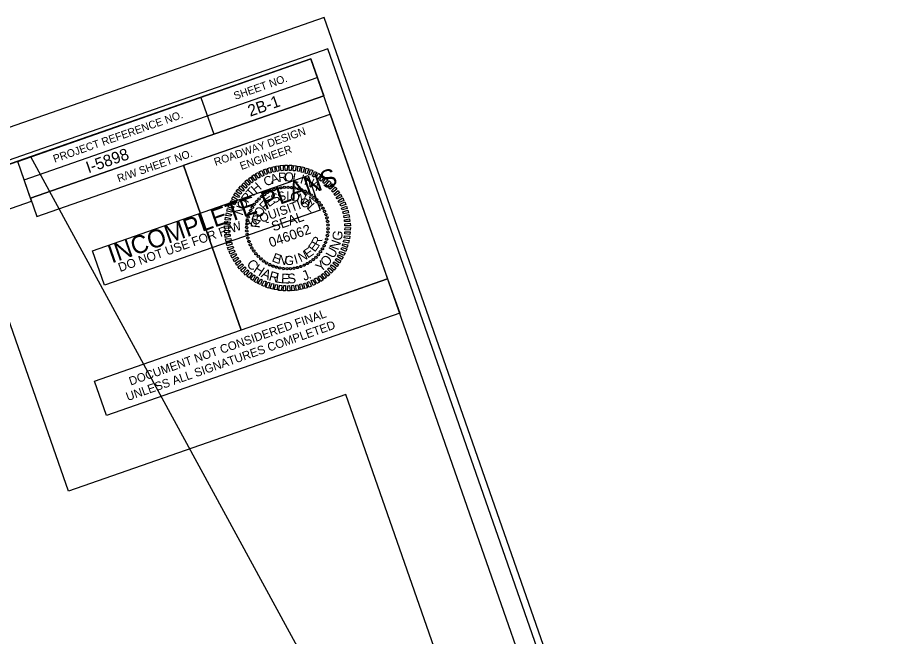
# Model space of a CAD drawing. Extents: x 1721700 to 1723652, y 970581 to 972169.
# Drawn here: x 1723091 to 1723650, y 971770 to 972169 of the extents above; entities that cross this region are included whole.
import ezdxf

# ---------------------------------------------------------------- set-up
doc = ezdxf.new("R2010")
doc.units = 0
for name, color, linetype in [('Default', 7, 'Continuous'), ('Old_Level_2', 7, 'Continuous'), ('Prop Dimension Text', 7, 'Continuous'), ('Sheet Clip Boundary CELL', 7, 'Continuous'), ('Sheet Data Field CELL', 7, 'Continuous'), ('Sheet Plan CELL', 7, 'Continuous'), ('Sheet Plot Border Inside CELL', 7, 'Continuous'), ('Sheet Plot Border Outside CELL', 7, 'Continuous'), ('Sheet Sticker Exception Certification CELL', 7, 'Continuous'), ('Sheet Sticker Incomplete CELL', 7, 'Continuous')]:
    doc.layers.add(name, color=color, linetype=linetype)

msp = doc.modelspace()

# ---------------------------------------------------------------- linework, layer by layer
at = {"layer": 'Old_Level_2'}
for p, q in [((1723261, 972059.49), (1723261, 972059.49)), ((1723263.22, 972059.81), (1723263.22, 972059.81)), ((1723265.54, 972059.89), (1723265.54, 972059.89)), ((1723267.83, 972059.73), (1723267.83, 972059.73)), ((1723270.1, 972059.45), (1723270.1, 972059.45)), ((1723248.55, 972053.95), (1723248.55, 972053.95)), ((1723250.4, 972055.3), (1723250.4, 972055.3)), ((1723252.41, 972056.49), (1723252.41, 972056.49)), ((1723254.41, 972057.56), (1723254.41, 972057.56)), ((1723256.55, 972058.41), (1723256.55, 972058.41)), ((1723258.77, 972059.06), (1723258.77, 972059.06)), ((1723272.32, 972058.88), (1723272.32, 972058.88)), ((1723274.53, 972058.18), (1723274.53, 972058.18)), ((1723276.59, 972057.27), (1723276.59, 972057.27)), ((1723278.66, 972056.2), (1723278.66, 972056.2)), ((1723280.52, 972054.93), (1723280.52, 972054.93)), ((1723243.88, 972048.94), (1723243.88, 972048.94)), ((1723245.33, 972050.76), (1723245.33, 972050.76)), ((1723246.88, 972052.44), (1723246.88, 972052.44)), ((1723282.33, 972053.49), (1723282.33, 972053.49)), ((1723284.02, 972051.93), (1723284.02, 972051.93)), ((1723285.53, 972050.26), (1723285.53, 972050.26)), ((1723286.88, 972048.42), (1723286.88, 972048.42)), ((1723240.63, 972042.95), (1723240.63, 972042.95)), ((1723241.54, 972045.01), (1723241.54, 972045.01)), ((1723242.62, 972047.08), (1723242.62, 972047.08)), ((1723288.07, 972046.4), (1723288.07, 972046.4)), ((1723289.14, 972044.4), (1723289.14, 972044.4)), ((1723239.37, 972038.53), (1723239.37, 972038.53)), ((1723239.94, 972040.74), (1723239.94, 972040.74)), ((1723289.99, 972042.26), (1723289.99, 972042.26)), ((1723290.63, 972040.05), (1723290.63, 972040.05)), ((1723291.07, 972037.81), (1723291.07, 972037.81)), ((1723238.93, 972033.96), (1723238.93, 972033.96)), ((1723239, 972031.65), (1723239, 972031.65)), ((1723239.09, 972036.25), (1723239.09, 972036.25)), ((1723265.2, 972033.62), (1723265.2, 972033.62)), ((1723291.39, 972035.59), (1723291.39, 972035.59)), ((1723291.46, 972033.28), (1723291.46, 972033.28)), ((1723239.32, 972029.43), (1723239.32, 972029.43)), ((1723239.76, 972027.19), (1723239.76, 972027.19)), ((1723290.45, 972026.5), (1723290.45, 972026.5)), ((1723291.03, 972028.71), (1723291.03, 972028.71)), ((1723291.3, 972030.99), (1723291.3, 972030.99)), ((1723240.41, 972024.98), (1723240.41, 972024.98)), ((1723241.25, 972022.84), (1723241.25, 972022.84)), ((1723242.32, 972020.84), (1723242.32, 972020.84)), ((1723287.77, 972020.16), (1723287.77, 972020.16)), ((1723288.85, 972022.23), (1723288.85, 972022.23)), ((1723289.76, 972024.29), (1723289.76, 972024.29)), ((1723243.51, 972018.82), (1723243.51, 972018.82)), ((1723244.86, 972016.98), (1723244.86, 972016.98)), ((1723246.37, 972015.31), (1723246.37, 972015.31)), ((1723283.51, 972014.79), (1723283.51, 972014.79)), ((1723285.06, 972016.48), (1723285.06, 972016.48)), ((1723286.51, 972018.3), (1723286.51, 972018.3)), ((1723248.06, 972013.75), (1723248.06, 972013.75)), ((1723249.87, 972012.31), (1723249.87, 972012.31)), ((1723251.73, 972011.04), (1723251.73, 972011.04)), ((1723253.8, 972009.97), (1723253.8, 972009.97)), ((1723255.87, 972009.06), (1723255.87, 972009.06)), ((1723275.98, 972009.68), (1723275.98, 972009.68)), ((1723277.98, 972010.75), (1723277.98, 972010.75)), ((1723279.99, 972011.94), (1723279.99, 972011.94)), ((1723281.84, 972013.29), (1723281.84, 972013.29)), ((1723258.07, 972008.36), (1723258.07, 972008.36)), ((1723260.29, 972007.79), (1723260.29, 972007.79)), ((1723262.57, 972007.51), (1723262.57, 972007.51)), ((1723264.85, 972007.35), (1723264.85, 972007.35)), ((1723267.17, 972007.43), (1723267.17, 972007.43)), ((1723269.39, 972007.75), (1723269.39, 972007.75)), ((1723271.63, 972008.18), (1723271.63, 972008.18)), ((1723273.84, 972008.83), (1723273.84, 972008.83))]:
    msp.add_line(p, q, dxfattribs=at)
for points in [[(1723248.79, 972066.91), (1723247.09, 972069.86), (1723248.69, 972070.67), (1723249.91, 972067.5)], [(1723251.15, 972068.06), (1723249.73, 972071.16), (1723251.37, 972071.71), (1723252.35, 972068.45)], [(1723253.52, 972068.88), (1723252.35, 972072.07), (1723253.98, 972072.62), (1723254.72, 972069.27)], [(1723256.03, 972069.64), (1723255.05, 972072.9), (1723256.78, 972073.21), (1723257.28, 972069.88)], [(1723258.53, 972070.12), (1723257.81, 972073.42), (1723259.52, 972073.77), (1723259.76, 972070.41)], [(1723261.23, 972070.5), (1723260.55, 972073.87), (1723262.36, 972074.09), (1723262.35, 972070.64)], [(1723263.82, 972070.73), (1723263.44, 972074.05), (1723265.14, 972074.12), (1723264.98, 972070.77)], [(1723266.36, 972070.66), (1723266.34, 972074.17), (1723267.93, 972074.09), (1723267.61, 972070.74)], [(1723268.91, 972070.55), (1723269.07, 972073.89), (1723270.84, 972073.77), (1723270.18, 972070.4)], [(1723271.58, 972070.25), (1723271.87, 972073.54), (1723273.65, 972073.24), (1723272.73, 972070.01)], [(1723273.98, 972069.63), (1723274.65, 972073.11), (1723276.3, 972072.55), (1723275.28, 972069.44)], [(1723276.54, 972068.9), (1723277.36, 972072.27), (1723279.03, 972071.66), (1723277.72, 972068.56)], [(1723278.96, 972068.07), (1723280.03, 972071.36), (1723281.64, 972070.62), (1723280.16, 972067.68)], [(1723242.27, 972062.84), (1723240.05, 972065.36), (1723241.41, 972066.37), (1723243.17, 972063.56)], [(1723244.39, 972064.34), (1723242.22, 972067.05), (1723243.76, 972068.01), (1723245.33, 972064.97)], [(1723246.54, 972065.75), (1723244.6, 972068.6), (1723246.16, 972069.35), (1723247.67, 972066.33)], [(1723281.36, 972067), (1723282.62, 972070.09), (1723284.23, 972069.34), (1723282.39, 972066.49)], [(1723283.73, 972065.87), (1723285.17, 972068.91), (1723286.69, 972067.97), (1723284.78, 972065.14)], [(1723285.91, 972064.5), (1723287.55, 972067.45), (1723289.01, 972066.37), (1723286.84, 972063.79)], [(1723287.92, 972062.96), (1723289.84, 972065.78), (1723291.31, 972064.66), (1723288.97, 972062.23)], [(1723236.7, 972057.38), (1723233.91, 972059.36), (1723235.14, 972060.71), (1723237.42, 972058.32)], [(1723238.38, 972059.34), (1723235.79, 972061.51), (1723237.06, 972062.75), (1723239.29, 972060.18)], [(1723240.15, 972061.17), (1723237.83, 972063.54), (1723239.08, 972064.67), (1723241.27, 972061.91)], [(1723290, 972061.27), (1723292.11, 972064), (1723293.31, 972062.72), (1723290.93, 972060.56)], [(1723291.75, 972059.52), (1723294.11, 972062.06), (1723295.32, 972060.73), (1723292.64, 972058.63)], [(1723293.49, 972057.54), (1723296.01, 972059.92), (1723297.11, 972058.6), (1723294.36, 972056.7)], [(1723232.27, 972050.96), (1723229.32, 972052.32), (1723230.06, 972053.93), (1723232.95, 972051.99)], [(1723233.67, 972053.2), (1723230.69, 972054.78), (1723231.64, 972056.3), (1723234.37, 972054.18)], [(1723234.99, 972055.36), (1723232.26, 972057.19), (1723233.19, 972058.6), (1723235.86, 972056.35)], [(1723295.14, 972055.48), (1723297.87, 972057.77), (1723298.76, 972056.26), (1723295.87, 972054.58)], [(1723296.6, 972053.34), (1723299.35, 972055.41), (1723300.26, 972053.85), (1723297.27, 972052.42)], [(1723230.26, 972046.14), (1723227, 972047.12), (1723227.61, 972048.79), (1723230.62, 972047.28)], [(1723231.29, 972048.64), (1723228.04, 972049.73), (1723228.85, 972051.31), (1723231.78, 972049.72)], [(1723297.91, 972051.15), (1723300.84, 972053.01), (1723301.61, 972051.4), (1723298.54, 972050.05)], [(1723299.07, 972048.9), (1723302.12, 972050.47), (1723302.83, 972048.84), (1723299.6, 972047.76)], [(1723228.73, 972041.23), (1723225.44, 972041.69), (1723225.91, 972043.43), (1723229.18, 972042.4)], [(1723229.47, 972043.74), (1723226.21, 972044.43), (1723226.62, 972046.19), (1723229.77, 972044.9)], [(1723300.03, 972046.47), (1723303.16, 972047.79), (1723303.78, 972046.12), (1723300.46, 972045.29)], [(1723300.88, 972044), (1723304.11, 972045.08), (1723304.61, 972043.42), (1723301.22, 972042.78)], [(1723301.51, 972041.55), (1723304.75, 972042.42), (1723305.17, 972040.68), (1723301.69, 972040.29)], [(1723228.18, 972036.07), (1723224.72, 972036.08), (1723224.89, 972037.87), (1723228.27, 972037.33)], [(1723228.33, 972038.69), (1723225.08, 972038.88), (1723225.25, 972040.68), (1723228.57, 972039.84)], [(1723302.04, 972038.91), (1723305.22, 972039.64), (1723305.49, 972037.84), (1723302.02, 972037.73)], [(1723228.13, 972030.92), (1723224.85, 972030.44), (1723224.59, 972032.18), (1723228.14, 972032.1)], [(1723227.99, 972033.55), (1723224.63, 972033.31), (1723224.7, 972035.07), (1723228.15, 972034.78)], [(1723302.4, 972033.69), (1723305.77, 972033.93), (1723305.69, 972032.17), (1723302.24, 972032.46)], [(1723302.27, 972036.32), (1723305.54, 972036.8), (1723305.8, 972035.06), (1723302.25, 972035.14)], [(1723228.36, 972028.33), (1723225.17, 972027.6), (1723224.9, 972029.4), (1723228.37, 972029.51)], [(1723228.89, 972025.69), (1723225.64, 972024.82), (1723225.22, 972026.56), (1723228.7, 972026.95)], [(1723301.67, 972026.01), (1723304.96, 972025.55), (1723304.48, 972023.81), (1723301.21, 972024.83)], [(1723302.07, 972028.55), (1723305.32, 972028.36), (1723305.14, 972026.56), (1723301.82, 972027.4)], [(1723302.22, 972031.17), (1723305.67, 972031.16), (1723305.5, 972029.37), (1723302.12, 972029.91)], [(1723229.51, 972023.24), (1723226.29, 972022.16), (1723225.79, 972023.82), (1723229.17, 972024.46)], [(1723230.37, 972020.77), (1723227.23, 972019.45), (1723226.62, 972021.12), (1723229.93, 972021.95)], [(1723300.14, 972021.1), (1723303.39, 972020.12), (1723302.78, 972018.45), (1723299.77, 972019.96)], [(1723300.92, 972023.5), (1723304.18, 972022.81), (1723303.78, 972021.05), (1723300.63, 972022.34)], [(1723231.32, 972018.34), (1723228.28, 972016.77), (1723227.56, 972018.4), (1723230.79, 972019.48)], [(1723232.48, 972016.09), (1723229.55, 972014.23), (1723228.79, 972015.84), (1723231.85, 972017.19)], [(1723233.79, 972013.9), (1723231.05, 972011.83), (1723230.14, 972013.39), (1723233.12, 972014.82)], [(1723298.12, 972016.28), (1723301.08, 972014.92), (1723300.33, 972013.31), (1723297.44, 972015.25)], [(1723299.11, 972018.6), (1723302.35, 972017.51), (1723301.54, 972015.93), (1723298.61, 972017.52)], [(1723235.25, 972011.76), (1723232.53, 972009.47), (1723231.64, 972010.98), (1723234.53, 972012.66)], [(1723236.9, 972009.7), (1723234.38, 972007.32), (1723233.28, 972008.64), (1723236.03, 972010.54)], [(1723293.69, 972009.86), (1723296.48, 972007.88), (1723295.25, 972006.53), (1723292.98, 972008.92)], [(1723295.4, 972011.88), (1723298.14, 972010.05), (1723297.2, 972008.64), (1723294.54, 972010.89)], [(1723296.72, 972014.04), (1723299.7, 972012.46), (1723298.75, 972010.94), (1723296.02, 972013.06)], [(1723238.64, 972007.72), (1723236.29, 972005.18), (1723235.07, 972006.51), (1723237.75, 972008.61)], [(1723240.4, 972005.97), (1723238.28, 972003.24), (1723237.08, 972004.52), (1723239.46, 972006.68)], [(1723242.47, 972004.28), (1723240.56, 972001.46), (1723239.08, 972002.58), (1723241.42, 972005.01)], [(1723244.49, 972002.74), (1723242.84, 971999.79), (1723241.39, 972000.87), (1723243.55, 972003.45)], [(1723288.12, 972004.4), (1723290.34, 972001.88), (1723288.98, 972000.87), (1723287.22, 972003.68)], [(1723290.24, 972006.07), (1723292.56, 972003.7), (1723291.31, 972002.57), (1723289.12, 972005.33)], [(1723292.02, 972007.9), (1723294.6, 972005.73), (1723293.33, 972004.49), (1723291.1, 972007.06)], [(1723246.66, 972001.37), (1723245.22, 971998.33), (1723243.7, 971999.27), (1723245.62, 972002.1)], [(1723249.03, 972000.24), (1723247.77, 971997.15), (1723246.16, 971997.9), (1723248.01, 972000.75)], [(1723251.43, 971999.17), (1723250.36, 971995.88), (1723248.75, 971996.62), (1723250.23, 971999.56)], [(1723253.86, 971998.34), (1723253.04, 971994.97), (1723251.36, 971995.58), (1723252.67, 971998.68)], [(1723256.41, 971997.61), (1723255.74, 971994.13), (1723254.09, 971994.69), (1723255.11, 971997.8)], [(1723276.87, 971998.36), (1723278.04, 971995.17), (1723276.41, 971994.62), (1723275.67, 971997.97)], [(1723279.24, 971999.18), (1723280.66, 971996.08), (1723279.03, 971995.53), (1723278.05, 971998.79)], [(1723281.6, 972000.33), (1723283.3, 971997.38), (1723281.71, 971996.57), (1723280.48, 971999.74)], [(1723283.85, 972001.49), (1723285.79, 971998.64), (1723284.23, 971997.89), (1723282.73, 972000.91)], [(1723286.01, 972002.9), (1723288.18, 972000.19), (1723286.63, 971999.23), (1723285.07, 972002.27)], [(1723258.81, 971996.99), (1723258.52, 971993.7), (1723256.74, 971994), (1723257.66, 971997.23)], [(1723261.49, 971996.69), (1723261.33, 971993.35), (1723259.55, 971993.47), (1723260.21, 971996.83)], [(1723264.04, 971996.58), (1723264.05, 971993.07), (1723262.46, 971993.15), (1723262.78, 971996.5)], [(1723266.57, 971996.51), (1723266.96, 971993.19), (1723265.26, 971993.12), (1723265.41, 971996.47)], [(1723269.16, 971996.74), (1723269.85, 971993.37), (1723268.03, 971993.15), (1723268.04, 971996.6)], [(1723271.86, 971997.12), (1723272.58, 971993.82), (1723270.87, 971993.47), (1723270.63, 971996.83)], [(1723274.36, 971997.6), (1723275.34, 971994.34), (1723273.61, 971994.03), (1723273.11, 971997.36)]]:
    msp.add_lwpolyline(points, close=True, dxfattribs=at)
for centre, major_axis in [((1723256.55, 972058.38), (-0.248, 0.711)), ((1723258.74, 972059.04), (-0.185, 0.73)), ((1723260.98, 972059.51), (-0.121, 0.743)), ((1723263.25, 972059.78), (-0.056, 0.751)), ((1723265.54, 972059.85), (0.01, 0.753)), ((1723267.82, 972059.72), (0.075, 0.749)), ((1723270.09, 972059.39), (0.14, 0.74)), ((1723272.32, 972058.86), (0.204, 0.725)), ((1723248.6, 972053.93), (-0.476, 0.583)), ((1723250.44, 972055.3), (-0.424, 0.622)), ((1723252.38, 972056.5), (-0.368, 0.657)), ((1723254.42, 972057.53), (-0.309, 0.687)), ((1723274.49, 972058.15), (0.267, 0.704)), ((1723276.59, 972057.24), (0.327, 0.678)), ((1723278.61, 972056.16), (0.385, 0.647)), ((1723280.52, 972054.91), (0.44, 0.611)), ((1723282.32, 972053.49), (0.491, 0.57)), ((1723243.91, 972048.94), (-0.611, 0.44)), ((1723245.33, 972050.74), (-0.57, 0.491)), ((1723246.89, 972052.41), (-0.525, 0.539)), ((1723283.98, 972051.92), (0.539, 0.525)), ((1723285.51, 972050.21), (0.583, 0.476)), ((1723286.88, 972048.38), (0.622, 0.424)), ((1723240.67, 972042.91), (-0.704, 0.267)), ((1723241.57, 972045.01), (-0.678, 0.327)), ((1723242.66, 972047.03), (-0.647, 0.385)), ((1723288.08, 972046.44), (0.657, 0.368)), ((1723289.11, 972044.39), (0.687, 0.309)), ((1723289.96, 972042.27), (0.711, 0.248)), ((1723239.1, 972036.25), (-0.749, 0.075)), ((1723239.43, 972038.51), (-0.74, 0.14)), ((1723239.95, 972040.74), (-0.725, 0.204)), ((1723290.62, 972040.08), (0.73, 0.185)), ((1723291.08, 972037.84), (0.743, 0.121)), ((1723238.97, 972033.96), (-0.753, 0.01)), ((1723239.04, 972031.68), (-0.751, -0.056)), ((1723291.29, 972030.99), (0.749, -0.075)), ((1723291.35, 972035.56), (0.751, 0.056)), ((1723291.42, 972033.28), (0.753, -0.01)), ((1723239.31, 972029.4), (-0.743, -0.121)), ((1723239.78, 972027.16), (-0.73, -0.185)), ((1723240.43, 972024.97), (-0.711, -0.248)), ((1723290.44, 972026.5), (0.725, -0.204)), ((1723290.96, 972028.73), (0.74, -0.14)), ((1723241.28, 972022.85), (-0.687, -0.309)), ((1723242.31, 972020.8), (-0.657, -0.368)), ((1723287.74, 972020.21), (0.647, -0.385)), ((1723288.82, 972022.23), (0.678, -0.327)), ((1723289.72, 972024.33), (0.704, -0.267)), ((1723243.52, 972018.86), (-0.622, -0.424)), ((1723244.89, 972017.03), (-0.583, -0.476)), ((1723246.41, 972015.32), (-0.539, -0.525)), ((1723248.08, 972013.75), (-0.491, -0.57)), ((1723283.5, 972014.83), (0.525, -0.539)), ((1723285.07, 972016.5), (0.57, -0.491)), ((1723286.48, 972018.3), (0.611, -0.44)), ((1723249.87, 972012.33), (-0.44, -0.611)), ((1723251.79, 972011.08), (-0.385, -0.647)), ((1723253.8, 972010), (-0.327, -0.678)), ((1723255.9, 972009.09), (-0.267, -0.704)), ((1723258.08, 972008.38), (-0.204, -0.725)), ((1723271.65, 972008.2), (0.185, -0.73)), ((1723273.84, 972008.86), (0.248, -0.711)), ((1723275.97, 972009.71), (0.309, -0.687)), ((1723278.01, 972010.74), (0.368, -0.657)), ((1723279.96, 972011.94), (0.424, -0.622)), ((1723281.79, 972013.31), (0.476, -0.583)), ((1723260.3, 972007.85), (-0.14, -0.74)), ((1723262.57, 972007.52), (-0.075, -0.749)), ((1723264.85, 972007.39), (-0.01, -0.753)), ((1723267.14, 972007.46), (0.056, -0.751)), ((1723269.41, 972007.73), (0.121, -0.743))]:
    msp.add_ellipse(centre, major_axis=major_axis, ratio=0.999708, dxfattribs=at)
at = {"layer": 'Prop Dimension Text'}
msp.add_lwpolyline([(1722958.72, 972001.56), (1723100.36, 972051.02), (1723091.43, 972076.58), (1722949.79, 972027.12)], close=True, dxfattribs=at)
at = {"layer": 'Sheet Clip Boundary CELL'}
for points in [[(1723600.74, 971158.62), (1723483.33, 971374.55), (1723099.98, 972079.55), (1721911.36, 971664.47), (1722084.53, 971168.86), (1722257.61, 970673.21), (1723579.34, 971134.77)], [(1723600.74, 971158.62), (1723483.33, 971374.55), (1723099.98, 972079.55), (1721911.36, 971664.47), (1722084.53, 971168.86), (1722257.61, 970673.21), (1723579.34, 971134.77)], [(1722257.53, 970673.18), (1723579.27, 971134.74), (1723302.82, 971926.38), (1723124.14, 971863.98), (1723054.41, 972063.64), (1721911.36, 971664.47)]]:
    msp.add_lwpolyline(points, close=True, dxfattribs=at)
at = {"layer": 'Sheet Plan CELL'}
for p, q in [((1723095.56, 972064.73), (1723284.43, 972130.67)), ((1723099.7, 972052.9), (1723288.55, 972118.87)), ((1723099.7, 972052.9), (1723288.55, 972118.87)), ((1723209.48, 972117.72), (1723217.77, 972094.14)), ((1723103.82, 972041.11), (1723292.67, 972107.07)), ((1723198.27, 972074.09), (1723235.36, 971967.92)), ((1723099.7, 972052.9), (1723103.82, 972041.11))]:
    msp.add_line(p, q, dxfattribs=at)
for points in [[(1723280.32, 972142.53), (1721864.15, 971647.99), (1722210.32, 970656.69), (1723626.47, 971151.23)], [(1723091.43, 972076.58), (1723280.32, 972142.53), (1723288.55, 972118.87), (1723099.7, 972052.9)], [(1723198.27, 972074.09), (1723292.67, 972107.07), (1723329.77, 972000.85), (1723235.37, 971967.87)]]:
    msp.add_lwpolyline(points, close=True, dxfattribs=at)
at = {"layer": 'Sheet Plot Border Inside CELL'}
msp.add_lwpolyline([(1722066.24, 970603.72), (1723639.08, 971152.98), (1723291.28, 972148.99), (1721718.43, 971599.74)], close=True, dxfattribs=at)
at = {"layer": 'Sheet Plot Border Outside CELL'}
msp.add_lwpolyline([(1722060.57, 970580.55), (1723649.94, 971135.58), (1723288.94, 972169.36), (1721699.56, 971614.33)], close=True, dxfattribs=at)
at = {"layer": 'Sheet Sticker Exception Certification CELL'}
for p, q in [((1723140.92, 971934.91), (1723329.77, 972000.86)), ((1723329.77, 972000.85), (1723337.52, 971978.66)), ((1723337.52, 971978.68), (1723148.66, 971912.73)), ((1723148.66, 971912.73), (1723140.92, 971934.91))]:
    msp.add_line(p, q, dxfattribs=at)
at = {"layer": 'Sheet Sticker Incomplete CELL'}
msp.add_lwpolyline([(1723147.43, 971996.75), (1723139.68, 972018.94), (1723278.46, 972067.4), (1723286.21, 972045.22)], close=True, dxfattribs=at)

# ---------------------------------------------------------------- texts
at = {"layer": 'Default'}
for s, rotation, p in [('G', 81.0495, (1723300.05, 972025.14)), ('N', 70.4786, (1723297.91, 972018.89)), ('U', 60.6845, (1723294.93, 972013.54)), ('O', 49.291, (1723290.38, 972008.07)), ('C', 316.4496, (1723238.46, 972009.74)), ('H', 325.8933, (1723242.73, 972005.67)), ('Y', 41.4923, (1723286.68, 972004.89)), ('A', 335.7331, (1723247.84, 972002.24)), ('R', 344.4458, (1723252.79, 971999.97)), ('L', 351.818, (1723257.21, 971998.66)), ('E', 358.0022, (1723261.02, 971998)), ('S', 5.0088, (1723265.4, 971997.75)), ('J', 22.2818, (1723276.04, 971999.43)), ('.', 27.4637, (1723279.08, 972000.54))]:
    msp.add_text(s, height=6.27, rotation=rotation, dxfattribs=at).set_placement(p)
at = {"layer": 'Old_Level_2'}
for s, height, rotation, p in [('C', 5.9, 26.4696, (1723251.55, 972060.19)), ('A', 5.9, 19.27, (1723255.32, 972061.91)), ('R', 5.9, 4.8708, (1723259.51, 972063.23)), ('O', 5.9, 357.6709, (1723263.07, 972063.71)), ('L', 5.9, 350.4706, (1723268.05, 972063.49)), ('I', 5.9, 343.2699, (1723272.9, 972062.6)), ('N', 5.9, 336.0686, (1723275.57, 972061.86)), ('T', 5.9, 48.0695, (1723242.23, 972052.68)), ('H', 5.9, 40.8692, (1723244.82, 972055.47)), ('A', 5.9, 328.8669, (1723279.53, 972060.03)), ('R', 5.9, 55.2702, (1723239.69, 972049.29)), ('E', 5.9, 36.8608, (1723253.35, 972046.86)), ('S', 5.9, 27.5053, (1723256.35, 972049.14)), ('S', 5.9, 18.1501, (1723259.86, 972050.49)), ('I', 5.9, 359.4393, (1723264.34, 972051.36)), ('O', 5.9, 350.0832, (1723266.55, 972051.4)), ('N', 5.9, 340.7263, (1723270.56, 972050.65)), ('N', 5.9, 69.6732, (1723236.22, 972041.32)), ('O', 5.9, 62.4715, (1723237.42, 972045)), ('F', 5.9, 46.2168, (1723250.75, 972044.23)), ('A', 5.9, 322.01, (1723274.3, 972049.13)), ('L', 5.9, 312.6506, (1723277.46, 972046.45)), ('R', 5.9, 74.2894, (1723247.75, 972037.1)), ('O', 5.9, 64.931, (1723248.58, 972040.14)), ('SEAL', 6.273, 19.2497, (1723256.15, 972031.4)), ('P', 5.9, 83.6486, (1723247.34, 972033.38)), ('046062', 6.275, 19.2497, (1723254.49, 972021.07)), ('R', 5.9, 62.7311, (1723285.45, 972021.31)), ('E', 5.9, 34.6615, (1723278.33, 972013.89)), ('E', 5.9, 53.3738, (1723282.82, 972017.72)), ('E', 5.9, 338.5266, (1723254.77, 972012.33)), ('N', 5.9, 347.8837, (1723258.69, 972010.77)), ('G', 5.9, 357.24, (1723263.23, 972009.93)), ('I', 5.9, 15.9509, (1723270.35, 972010.44)), ('N', 5.9, 25.3061, (1723273.69, 972011.51))]:
    msp.add_text(s, height=height, rotation=rotation, dxfattribs=at).set_placement(p)
at = {"layer": 'Sheet Data Field CELL'}
for s, p in [('2B-1', (1723241.18, 972105.29)), ('  I-5898 ', (1723131.73, 972067.01))]:
    msp.add_text(s, height=7.5, rotation=19.2497, dxfattribs=at).set_placement(p)
at = {"layer": 'Sheet Plan CELL'}
for s, height, p in [('SHEET NO.', 5, (1723231.58, 972116.16)), ('PROJECT REFERENCE NO.', 5.0001, (1723115.27, 972075.66)), ('ROADWAY DESIGN', 5.0001, (1723218.91, 972073.58)), ('R/W SHEET NO.', 5.0001, (1723156.54, 972063.01)), ('ENGINEER', 5, (1723235.61, 972070.99))]:
    msp.add_text(s, height=height, rotation=19.2497, dxfattribs=at).set_placement(p)
at = {"layer": 'Sheet Sticker Exception Certification CELL'}
for s, p in [('DOCUMENT NOT CONSIDERED FINAL', (1723164.22, 971932.09)), ('UNLESS ALL SIGNATURES COMPLETED', (1723162.33, 971922.11))]:
    msp.add_text(s, height=5.5, rotation=19.2497, dxfattribs=at).set_placement(p)
at = {"layer": 'Sheet Sticker Incomplete CELL'}
for s, height, p in [('INCOMPLETE PLANS', 11.52, (1723152.02, 972010.75)), ('DO NOT USE FOR R/W ACQUISITION', 5.76, (1723157.38, 972005.26))]:
    msp.add_text(s, height=height, rotation=19.2497, dxfattribs=at).set_placement(p)

doc.saveas('drawing.dxf')
